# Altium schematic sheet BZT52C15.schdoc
size 127 x 101 mm
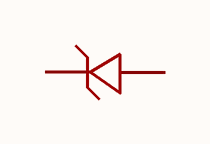
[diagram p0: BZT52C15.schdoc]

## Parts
D?  bzt52c15_c173427  [SOD-123_L2.7-W1.6-LS3.7-RD]  (value not drawn)

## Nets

Not connected (* = marked no-connect by the designer): D? 1(K) 2(A)

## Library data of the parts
D? = bzt52c15_c173427: 二极管配置:1个独立式;稳压值(标称值):15V;稳压值(范围):14.25V~15.75V;耗散功率(Pd):500mW;; Manufacturer: MDD(辰达半导体); AddInBom: yes; ModelId: ad7e39f9e5534b3c96ffdc5532ebb493; ModelName: SOD-123_L2.7-W1.6-H1.4-LS3.7; ModelTransform: 146.026,62.992,0,180,0,0,0.0005,0,0; Diode Configuration: 1个独立式; Zener Voltage(Nom): 15V; Reverse Leakage Current (Ir): 100nA@11V; Pd - Power Dissipation: 500mW; Impedance(Zzt): 40Ω; Tolerance: ±5%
